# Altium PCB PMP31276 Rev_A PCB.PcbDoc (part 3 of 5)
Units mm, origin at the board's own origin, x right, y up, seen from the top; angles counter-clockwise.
Board outline 228.6 x 203.2 mm, 4 copper layers (Top Layer, Layer 1, Layer 2, Bottom Layer), stack 1.998 mm thick; 375 components, 187 nets, 994 pads, 546 vias.
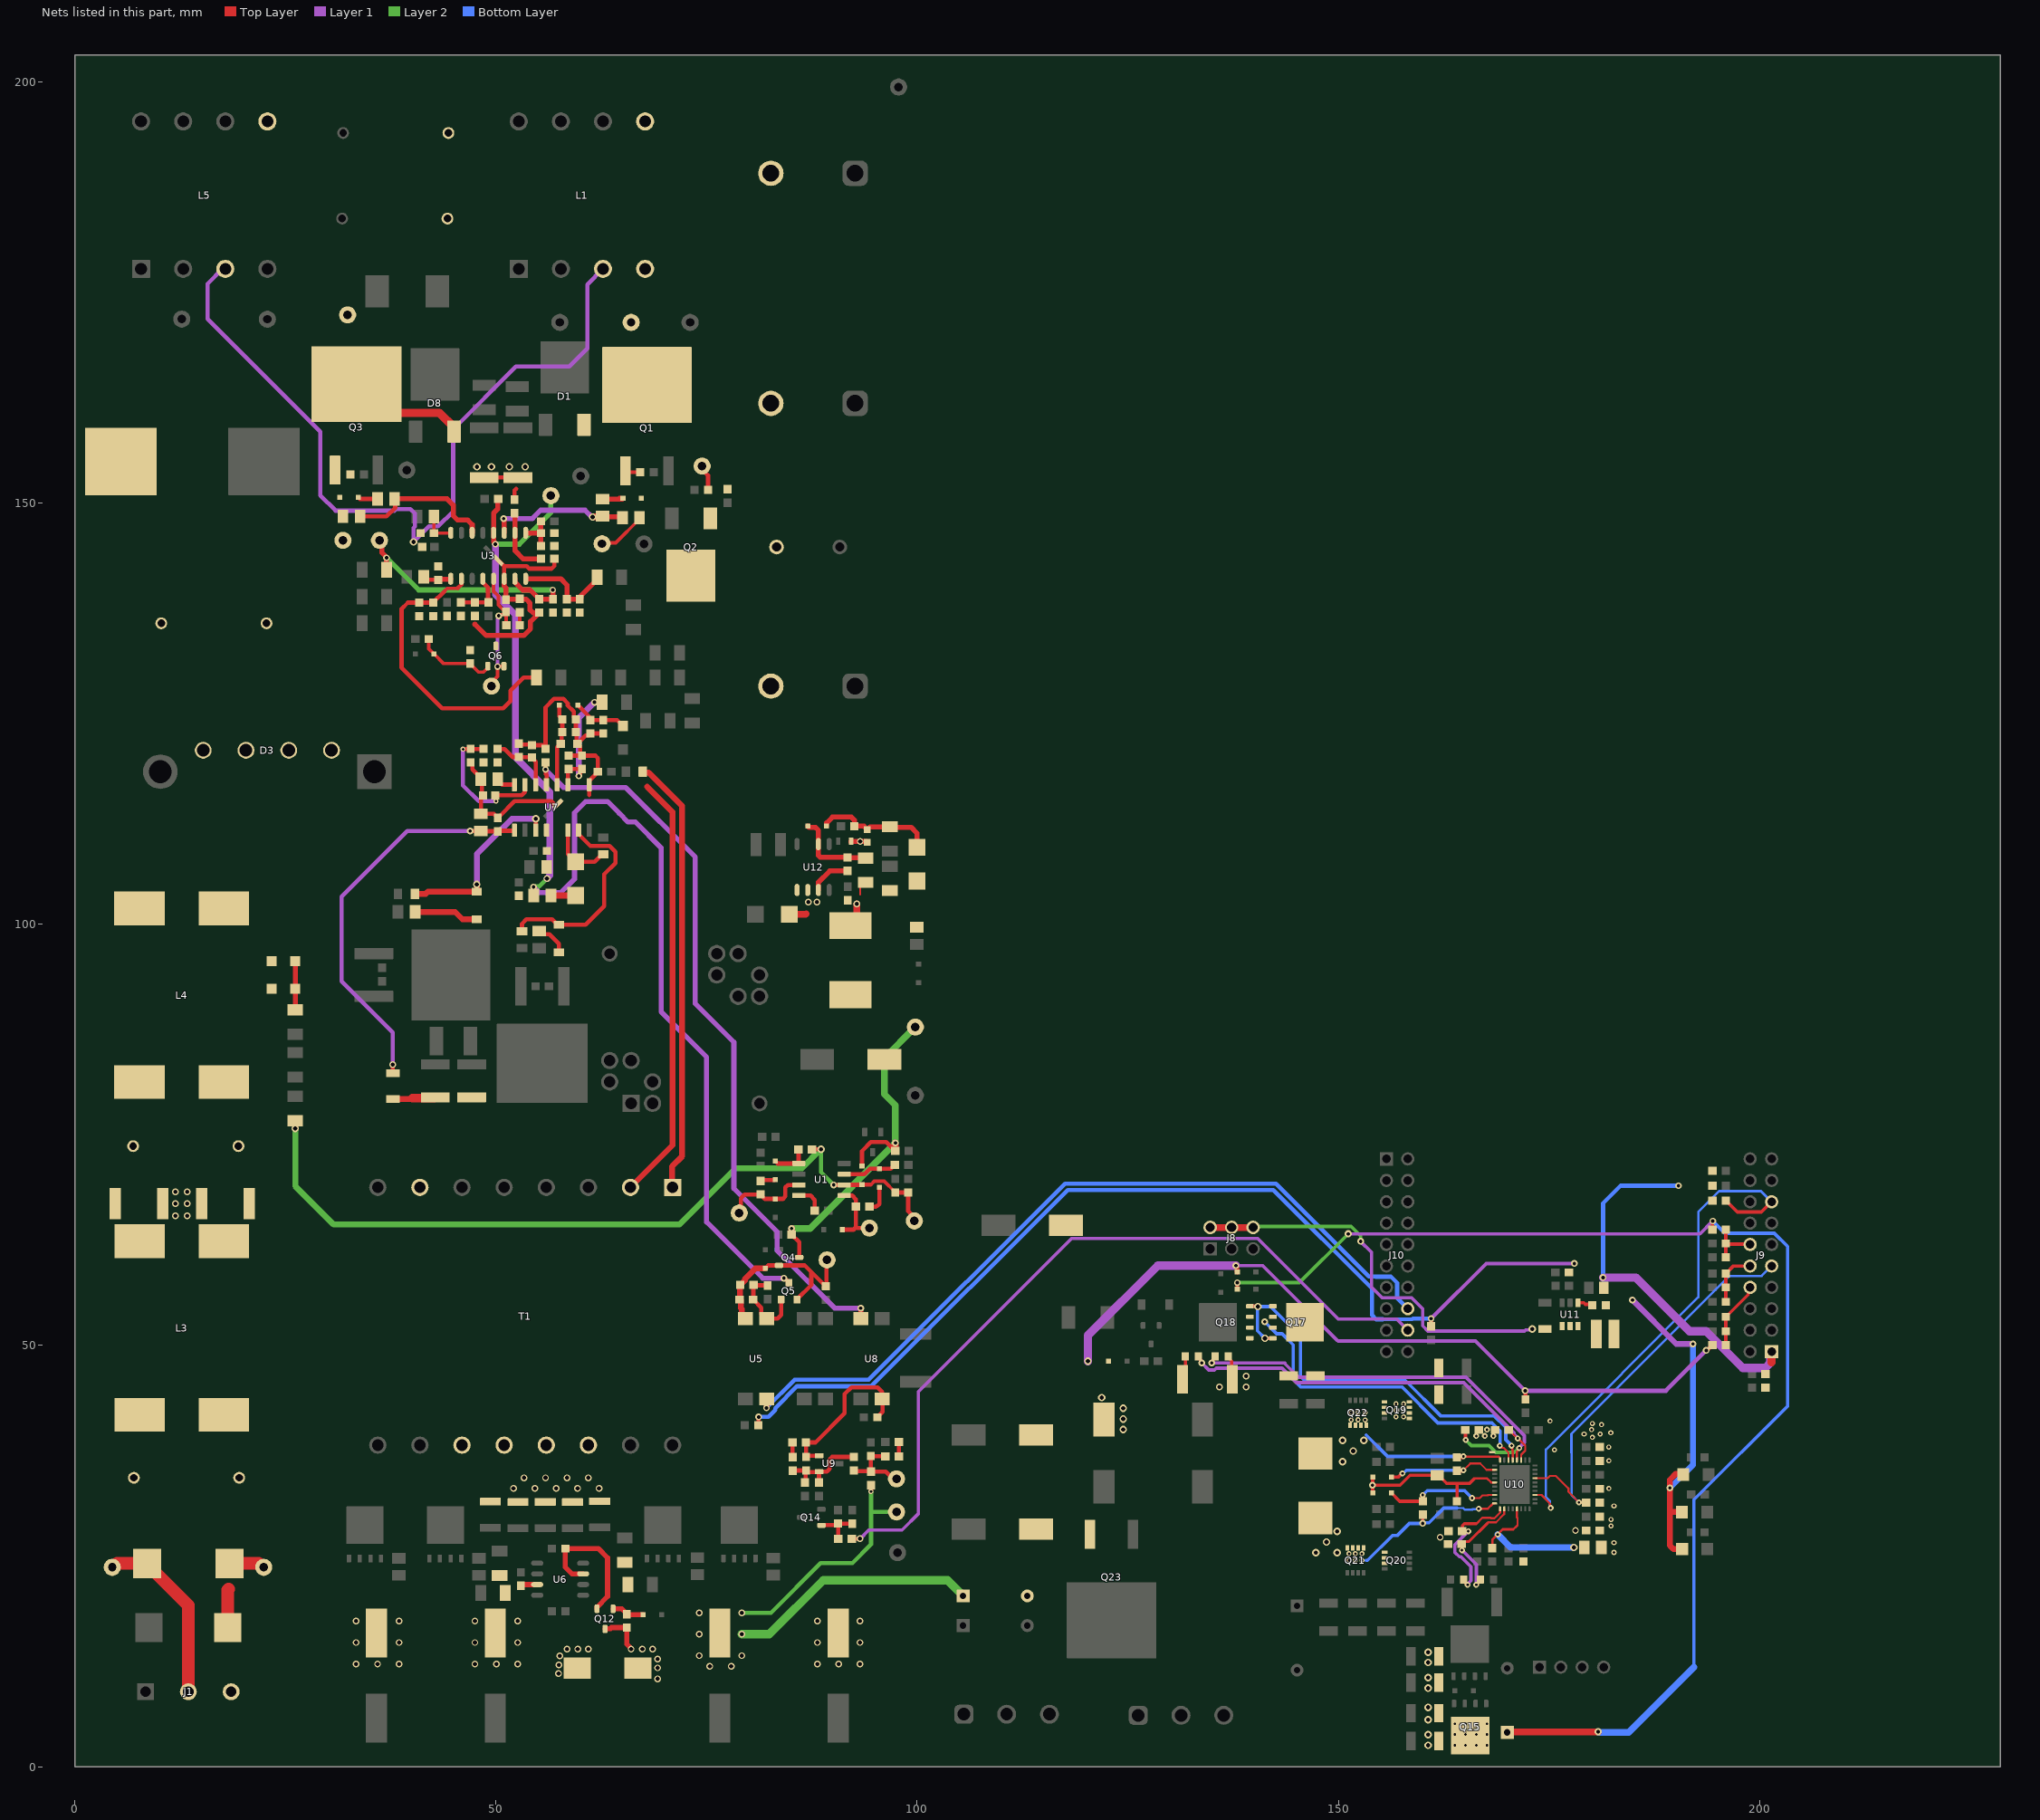
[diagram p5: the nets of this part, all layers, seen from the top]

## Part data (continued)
R100: library part CMP-0025067-3, "RES, 2.58 k, 0.5%, 0.1 W, 0603", Manufacturer="Yageo America", Power_W=100mW, TempCo="50 ppm/C", Tolerance_%=0.5%, Value2=0.1W, Value_Code=2k58, ValueDisplayed=2.58k
R101: library part CMP-0022941-4, "RES, 249 k, 1%, 0.1 W, 0603", Manufacturer=Yageo, Power_W=100mW, Supplier Part Number 1=311-249KHRCT-ND, TempCo="100 ppm/C", Tolerance_%=1%, Value2=0.1W, Value_Code=249k
R103: library part CMP-0025339-3, "RES, 4.22 k, 0.5%, 0.1 W, 0603", Manufacturer="Yageo America", Power_W=100mW, TempCo="50 ppm/C", Tolerance_%=0.5%, Value2=0.1W, Value_Code=4k22, ValueDisplayed=4.22k
R107: library part CMP-0023232-5, "RES, 66.5 k, 1%, 0.1 W, 0603", Manufacturer=Yageo, Power_W=100mW, Supplier Part Number 1=311-66.5KHRCT-ND, TempCo="100 ppm/C", Tolerance_%=1%, Value2=0.1W, Value_Code=66k5, ValueDisplayed=66.5k
R108: library part CMP-0022236-4, "RES, 24.3 k, 1%, 0.1 W, AEC-Q200 Grade 0, 0603", Manufacturer=Vishay-Dale, Power_W=100mW, Supplier Part Number 1=541-24.3KHCT-ND, TempCo="100 ppm/C", Tolerance_%=1%, Value2=0.1W, Value_Code=24k3, ValueDisplayed=24.3k
R109: library part CMP-0023155-5, "RES, 4.99 k, 1%, 0.1 W, 0603", Manufacturer=Yageo, Power_W=100mW, Supplier Part Number 1=311-4.99KHRCT-ND, TempCo="100 ppm/C", Tolerance_%=1%, Value2=0.1W, Value_Code=4k99, ValueDisplayed=4.99k
R110: library part CMP-0016277-2, "RES, 1.00 k, 1%, 0.75 W, AEC-Q200 Grade 0, 2010", Manufacturer=Vishay-Dale, Power_W=750mW, Supplier Part Number 1=541-1.00KACCT-ND, TempCo="100 ppm/C", Tolerance_%=1%, Value2=0.75W, Value_Code=1k00, ValueDisplayed=1.00k
R111: library part CMP-0024096-3, "RES, 30.1 k, 0.1%, 0.1 W, 0603", Manufacturer="Yageo America", Power_W=100mW, TempCo="25 ppm/C", Tolerance_%=0.1%, Value2=0.1W, Value_Code=30k1, ValueDisplayed=30.1k
R112: library part CMP-0024368-2, "RES, 5.23 k, 0.1%, 0.1 W, 0603", Manufacturer="Yageo America", Power_W=100mW, TempCo="25 ppm/C", Tolerance_%=0.1%, Value2=0.1W, Value_Code=5k23, ValueDisplayed=5.23k
R113: library part CMP-0086261-1, "RES, 100 k, 0.5%, 0.1 W, AEC-Q200 Grade 0, 0603", Manufacturer=Vishay-Dale, Power_W=100mW, TempCo="50 ppm/C", Tolerance_%=0.5%, Value2=0.1W, Value_Code=100k
R114 R132: library part CMP-0023167-5, "RES, 51.0 k, 1%, 0.1 W, 0603", Manufacturer=Yageo, Power_W=100mW, Supplier Part Number 1=311-51.0KHRCT-ND, TempCo="100 ppm/C", Tolerance_%=1%, Value2=0.1W, Value_Code=51k0, ValueDisplayed=51.0k
R116 R117: library part CMP-0017472-3, "RES, 237 k, 1%, 0.25 W, AEC-Q200 Grade 0, 1206", Manufacturer=Panasonic, Power_W=250mW, Supplier Part Number 1=P237KFCT-ND, TempCo="100 ppm/C", Tolerance_%=1%, Value2=0.25W, Value_Code=237k
R118: library part CMP-0022851-5, "RES, 18.7 k, 1%, 0.1 W, 0603", Manufacturer=Yageo, Power_W=100mW, Supplier Part Number 1=311-18.7KHRCT-ND, TempCo="100 ppm/C", Tolerance_%=1%, Value2=0.1W, Value_Code=18k7, ValueDisplayed=18.7k
R120: library part CMP-0021276-3, "RES, 47.5, 1%, 0.125 W, AEC-Q200 Grade 0, 0805", Manufacturer=Vishay-Dale, Power_W=125mW, Supplier Part Number 1=541-47.5CCT-ND, TempCo="100 ppm/C", Tolerance_%=1%, Value2=0.125W, Value_Code=47R5, ValueDisplayed=47.5
R125 R127 R128: library part CMP-0022746-5, "RES, 10.0 k, 1%, 0.1 W, 0603", Manufacturer=Yageo, Power_W=100mW, Supplier Part Number 1=311-10.0KHRCT-ND, TempCo="100 ppm/C", Tolerance_%=1%, Value2=0.1W, Value_Code=10k0, ValueDisplayed=10.0k
R126 R129 R130: library part CMP-0022008-4, "RES, 110 k, 1%, 0.1 W, AEC-Q200 Grade 0, 0603", Manufacturer=Vishay-Dale, Power_W=100mW, Supplier Part Number 1=541-110KHCT-ND, TempCo="100 ppm/C", Tolerance_%=1%, Value2=0.1W, Value_Code=110k
RT1: library part CMP-0002554-2, "Thermistor NTC, 22 ohm, 20%, 15x7mm", Manufacturer=TDK, Power_W=3.1W, Supplier Part Number 1=495-3054-ND, Tolerance_%=20%
RV1: library part CMP-0002101-2, "Varistor, 275VAC, 1200A, SMD", Manufacturer=Littelfuse, Supplier Part Number 1=F3550CT-ND
T1: library part CMP-0120632-1, "TRANSFORMER", Manufacturer=Wurth, Operating Temperature Range="-40°C to +125°C"
TP1 TP2 TP17 TP23 TP26: library part CMP-0055137-2, "Test Point, Miniature, Red, TH", Color=Red, Manufacturer="Keystone Electronics", Supplier Part Number 1=36-5000-ND
TP3 TP6 TP10 TP11 TP12 TP13 TP14 TP16 TP18 TP19 TP20 TP21 TP22 TP25: library part CMP-0055141-2, "Test Point, Miniature, Yellow, TH", Color=Yellow, Manufacturer="Keystone Electronics", Supplier Part Number 1=36-5004-ND
TP4 TP7 TP9 TP15 TP24 TP27: library part CMP-0055138-2, "Test Point, Miniature, Black, TH", Color=Black, Manufacturer="Keystone Electronics", Supplier Part Number 1=36-5001-ND
TP5 TP8: library part CMP-0055139-2, "Test Point, Miniature, White, TH", Color=White, Manufacturer="Keystone Electronics", Supplier Part Number 1=36-5002-ND
U1: library part CMP-0089002-1, "Dual Rail-to-rail Comparator with push-pull outputs, 8-SOIC", Manufacturer="Texas Instruments", Operating Temperature Range="-40°C to +125°C"
U2: library part CMP-0033016-1, "Precision Micropower Shunt Voltage Reference, 1% accuracy, 5 V, 15 ppm / degC, 15 mA, -40 to 125 degC, 3-pin SOT-23 (DBZ), Green (RoHS & no Sb/Br)", Manufacturer="Texas Instruments", Rating=Catalog, Temp Coeff(Max)(ppm/ degree C)=150, Temp Coeff(Typ)(ppm/ degree C)=15
U3: library part CMP-0861100-1, "Natural Interleaving Transition Mode PFC Controller with High Light Load Efficiency Supporting High-Frequency Switching up-to 1MHz, D0016A (SOIC-16)", Alternate Manufacturer="Texas Instruments"
U4 U5 U8: library part CMP-0006172-3, "Optocoupler, 5.3 kV, 63-125% CTR, SMT", Manufacturer=Vishay-Semiconductor, Supplier Part Number 1=751-1346-1-ND, Voltage_Isolation_Vrms=5.3kV
U6: library part CMP-0079610-1, "High Performance Synchronous Rectifier Driver for LLC Resonant Converter, D0008A (SOIC-8)", Alternate Manufacturer="Texas Instruments"
U7: library part CMP-0095299-1, "750kHz Wide VIN/VOUT Range LLC Controller Optimized for Light Load Efficiency", Manufacturer="Texas Instruments", Max Supply Voltage=18.5V, Operating Temperature Range="-40°C to +150°C", Switching Frequency=30-750kHz
U9: library part CMP-0084733-1, "High Bandwidth Low-Iq Programmable Shunt Regulator, DBZ0003A (SOT-23-3)", Alternate Manufacturer="Texas Instruments"
U10: library part CMP-0093459-1, Manufacturer="Texas Instruments", Operating Temperature Range=to
U11: library part CMP-0065097-3, "4V to 36 V 0.6 A Synchronous Step-Down Converter, DBV0006A (SOT-23-6)", Alternate Manufacturer="Texas Instruments", Alternate PartNumber=TPS560430XDBVT
U12: library part CMP-0067241-2, "700V Flyback Switcher with Constant-Voltage Constant-Current and Primary-side Control, D0007A (SOIC-7)", Alternate Manufacturer="Texas Instruments", Alternate PartNumber=UCC28910D

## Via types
v1: diameter 0.8, hole 0.5, Top Layer to Bottom Layer, tented both sides, 185 vias
v2: diameter 0.9, hole 0.5, Top Layer to Bottom Layer, tented both sides, 166 vias
v3: diameter 0.6, hole 0.3, Top Layer to Bottom Layer, tented both sides, 64 vias
v4: diameter 0.8, hole 0.4, Top Layer to Bottom Layer, tented both sides, 55 vias
v5: diameter 0.7, hole 0.3, Top Layer to Bottom Layer, tented both sides, 55 vias
v6: diameter 0.5, hole 0.2, Top Layer to Bottom Layer, 16 vias
v7: diameter 0.9, hole 0.5, Top Layer to Bottom Layer, tented bottom, 3 vias
v8: diameter 0.864, hole 0.406, Top Layer to Bottom Layer, tented both sides, 2 vias

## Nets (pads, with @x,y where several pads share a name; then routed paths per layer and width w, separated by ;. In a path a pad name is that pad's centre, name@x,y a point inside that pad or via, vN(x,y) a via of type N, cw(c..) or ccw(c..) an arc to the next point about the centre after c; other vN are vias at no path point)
3V3: C93.1 C99.1 C100.2 D26.2 D27.2 D28.2 J9.1 L9.2 R39.2 R114.2 R121.2 R122.2 R123.2 R131.2 | length 207.2
  Top Layer w0.5: R39.2@81.135,40.513 81.161,40.539 81.161,41.479 v4(81.187,41.505) ; R131.2@161.006,52.258 v4(161.006,53.187)
  Top Layer w0.7: D26.2@190.778,30.226 189.434,30.226 189.357,30.149 ; D27.2@190.805,25.832 189.767,25.832 189.357,26.242 189.357,30.149 ; D28.2@190.924,34.668 190.816,34.776 190.078,34.776 189.357,34.055 v4(189.357,33.092) 189.357,30.149
  Top Layer w1: 201.422,48.006 J9.1@201.422,49.276
  Layer 1 w0.45: v4(161.006,53.187) 167.546,59.727 v4(178.004,59.727)
  Layer 1 w0.7: v4(184.912,55.379) 190.118,50.173 v4(192.109,50.173)
  Layer 1 w1: v4(181.419,58.055) 185.317,58.055 191.684,51.689 193.649,51.689 198.004,47.334 200.686,47.334 201.295,47.942 201.295,49.149 J9.1@201.422,49.276
  Bottom Layer w0.45: 155.286,53.105 155.299,53.092 158.766,53.092 158.86,53.187 v4(161.006,53.187)
  Bottom Layer w0.5: v4(81.187,41.505) 81.211,41.528 82.337,41.528 83.138,42.329 83.138,42.541 85.757,45.16 94.559,45.16 117.859,68.461 142.293,68.461 153.993,56.761 153.993,53.597 154.484,53.105 155.286,53.105 ; v4(181.419,58.055) 181.419,66.865 183.515,68.961 v4(190.373,68.961)
  Bottom Layer w0.7: v4(189.357,33.092) 192.109,35.845 v4(192.109,50.173)
5Vp: C52.1 R64.1 R69.1 U7.8 | length 2.3
  Top Layer w0.5: C52.1@50.216,117.24 50.216,117.075 50.721,116.57 U7.8@52.181,116.57
15Vp: C98.1 D9.1 D35.2 L10.2 Q4.3 R10.2 R12.2 R117.2 R120.2 TP26.1 | length 43.7
  Top Layer w0.5: R12.2@85.088,63.148 85.113,63.148 85.988,62.273 Q4.3@85.988,60.452 ; D9.1@93.448,71.283 93.448,73.069 94.517,74.138 96.327,74.138 97.365,73.1 R10.2@97.39,73.1
  Top Layer w0.8: R12.2@85.088,63.148 85.09,63.15 v4(85.09,63.881) ; R10.2@97.39,73.1 97.418,73.128 v4(97.418,74.027)
  Layer 2 w0.8: v4(85.09,63.881) 87.272,63.881 v4(97.418,74.027) 97.418,78.528 96.084,79.862 96.084,84.094 TP26.1@99.78,87.79
15Vp-sw: C19.1 C48.1 C49.1 C50.1 Q5.3 R63.2 TP17.1 U3.12 U7.12 | length 147.7
  Top Layer w0.5: v4(54.445,104.424) 54.464,104.405 54.464,103.427 R63.2@54.483,103.408 ; v4(84.179,57.992) 84.236,57.934 84.352,57.934 84.788,57.498 Q5.3@84.788,57.448
  Top Layer w0.6: v4(49.923,145.118) 49.923,145.172 49.71,145.385 U3.12@49.71,146.461 49.71,148.8 50.209,149.299 50.209,150.427 C19.1@50.263,150.481
  Layer 1 w0.6: v4(54.445,104.424) 54.499,104.424 55.148,103.775 57.724,103.775 59.32,105.371 59.32,113.24 60.648,114.568 63.235,114.568 64.622,113.181 64.622,113.175 65.667,112.13 66.556,112.13 69.603,109.083 69.603,89.626 75.008,84.222 75.008,64.653 81.669,57.992 v4(84.179,57.992) ; TP17.1@56.481,150.842 TP17.1@56.515,150.876
  Layer 1 w0.8: v4(49.923,145.118) 49.923,139.099 52.287,136.734 52.287,119.822 56.409,115.7 56.409,105.792 v1(56.049,105.431)
  Layer 2 w0.5: v4(54.445,104.424) 54.502,104.481 55.099,104.481 v1(56.049,105.431)
  Layer 2 w0.6: v4(49.923,145.118) 52.775,145.118 56.515,148.858 TP17.1@56.515,150.876
24V/27.6V: J10.39 R84.1 | length 93.8
  Top Layer w0.4: R84.1@92.24,27.051 v1(93.218,27.051)
  Layer 1 w0.4: v1(93.218,27.051) 94.251,28.084 98.199,28.084 100.152,30.038 100.152,44.526 118.323,62.697 140.429,62.697 149.983,53.142 156.916,53.142 J10.39@158.242,51.816
+24V: C38.1 C64.1 C65.1 C66.1 C67.1 C85.1 C86.2 D32.2 J6.1 J11.1 L7.2 Q12.3 Q15.5 Q15.6 Q15.7 Q15.8 Q15.9@165.648,3.685 R60.2 R65.2 R99.2 R126.1 TP23.1 U10.33 | length 231.6
  Top Layer w0.25: 170.748,28.156 170.981,28.389 170.992,28.389 171.272,28.668 171.272,29.503 171.191,29.584 U10.33@171.191,30.595
  Top Layer w0.3: R99.2@168.275,25.946 168.275,26.924 v5(168.91,27.559) 169.507,28.156 170.748,28.156
  Top Layer w0.35: R99.2@168.02,26.04 R99.2@168.02,26.065
  Top Layer w0.4: D32.2@138.002,56.681 v4(138.002,57.456) ; R126.1@194.399,63.754 194.418,63.773 194.418,64.751 v4(194.437,64.77)
  Top Layer w0.5: v3(94.517,32.664) R65.2@94.517,33.414
  Top Layer w0.6: Q12.3@62.944,16.345 62.944,16.369 63.586,16.369 63.721,16.504 R60.2@65.535,16.504 65.535,14.529 66.04,14.024 v1(66.04,13.97)
  Top Layer w0.8: J11.1@170.053,4.064 170.116,4.127 180.833,4.127 v8(180.845,4.14)
  Layer 1 w0.4: v8(151.158,63.246) 192.913,63.246 v4(194.437,64.77)
  Layer 2 w0.4: v4(138.002,57.456) 145.367,57.456 v8(151.158,63.246)
  Layer 2 w0.5: v1(79.193,18.255) 82.643,18.255 88.543,24.155 92.32,24.155 94.517,26.353 94.517,30.226 ; v3(94.517,32.664) 94.517,30.226 ; TP23.1@97.536,30.226 94.517,30.226
  Layer 2 w1: v1(79.193,15.715) 82.428,15.715 88.838,22.125 103.595,22.125 J6.1@105.453,20.267
  Bottom Layer w0.4: 192.211,11.811 192.211,31.683 203.327,42.799 203.327,61.747 201.752,63.322 195.885,63.322 v4(194.437,64.77)
  Bottom Layer w0.8: v5(168.91,27.559) 170.448,26.021 v2(177.953,26.021) ; v8(180.845,4.14) 180.921,4.064 184.464,4.064 192.211,11.811
  other v1: 69.182,10.429 69.182,11.726 75.383,11.905 77.923,11.905 69.182,12.763 74.113,13.175 79.193,13.175 67.374,13.97 68.58,13.97 74.113,15.715 74.113,18.255 178.15,28.02
  other v2: 160.655,2.54 160.655,3.81 160.655,5.581 160.655,7.04 160.655,9.312 160.655,10.583 160.655,12.368 160.655,13.581
  other v3: 163.83,2.54 165.1,2.54 166.37,2.54 167.64,2.54 163.83,3.81 165.1,3.81 166.37,3.81 167.64,3.81 163.83,5.08 165.1,5.08 166.37,5.08 167.64,5.08
+24Vsw: C8.2 C12.2 C35.1 C36.1 C37.1 C39.2 C40.2 C41.2 L7.1 T1.11 T1.12 T1.13 T1.14
  other v1: 57.435,11.066 57.484,12.088 33.401,12.192 35.941,12.192 38.481,12.192 47.498,12.192 50.038,12.192 52.578,12.192 88.138,12.192 90.678,12.192 93.218,12.192 57.568,13.166 58.42,13.97 59.702,13.97 60.96,13.97 33.401,14.732 38.481,14.732 47.498,14.732 52.578,14.732 88.138,14.732 93.218,14.732 33.401,17.272 38.481,17.272 47.498,17.272 52.578,17.272 88.138,17.272 93.218,17.272 52.07,33.02 54.61,33.02 57.15,33.02 59.69,33.02 62.23,33.02 53.34,34.29 55.88,34.29 58.42,34.29 60.96,34.29
AC_DC_on: J10.38 U5.2 | length 95.5
  Top Layer w0.5: U5.2@82.11,43.628 U5.2@82.145,43.663
  Top Layer w0.7: v4(82.11,42.58) U5.2@82.11,43.628
  Bottom Layer w0.5: v4(82.11,42.58) 85.445,45.914 94.246,45.914 117.547,69.215 142.605,69.215 153.624,58.195 154.392,58.195 154.428,58.16 156.225,58.16 156.978,57.407 156.978,55.62 J10.38@158.242,54.356
AGND: C69.2 C70.1 C82.1 C83.2 C85.2 C86.1 NT1.2 R103.1 R107.1 R108.1 R109.1 R111.1 R124.1
  other v1: 162.077,27.231
  other v3: 182.719,25.432 182.719,26.584 182.372,28.569 182.372,29.337 182.719,30.949 182.118,33.02 182.118,36.322 175.641,37.592 182.091,37.945 180.144,39.089 179.166,39.48 181.087,39.48 182.339,39.625 180.058,40.005 181.228,40.597 180.144,40.736 175.133,41.021
  other v5: 166.37,39.243 167.386,39.243 168.402,39.243 167.64,40.005
AGND1: C18.2 C20.2 C21.2 C22.2 C23.2 C24.1 C25.2 C26.2 C28.1 C29.2 C30.2 C31.2 L1.3 L5.3 NT2.2 Q6.3 R26.1 R33.1 R40.1 R41.1 R42.1 R46.1 U3.6 | length 122.5
  Top Layer w0.5: NT2.2@50.255,143.208 50.255,143.203 50.96,142.498 ; U3.6@50.961,141.031 U3.6@50.98,141.011 ; U3.6@50.98,141.031 50.98,142.478 50.96,142.498 ; C20.2@56.934,143.383 56.934,142.536 56.615,142.217 53.928,142.217 53.647,142.498 50.96,142.498
  Top Layer w0.6: 47.498,135.603 48.836,134.265 53.283,134.265 54.094,135.077 54.094,135.946 55.118,136.97 C23.2@55.118,136.995 55.044,137.069 54.957,136.982 54.381,136.982 54.047,137.316 54.047,138.105 53.557,138.595 52.87,138.595 C26.2@52.832,138.633 52.776,138.577 51.237,138.577 C24.1@51.181,138.521 51.181,139.924 50.98,140.125 U3.6@50.98,141.011
  Layer 1 w0.5: L5.3@17.86,177.8 17.526,177.8 15.748,176.022 15.748,171.876 29.155,158.469 29.155,150.894 30.95,149.099 37.96,149.099 38.16,149.299 39.839,149.299 40.366,148.772 40.366,147.216 40.195,147.046 v2(40.195,145.382) 42.036,147.222 43.121,147.222 44.921,149.022 44.921,158.768 52.375,166.222 58.717,166.222 60.851,168.356 60.851,175.95 L1.3@62.701,177.8
AGND2: C52.2 C53.1 C55.2 C56.1 C57.2 C58.2 C59.2 C60.2 NT3.2 R58.1 R67.1 R75.1 R76.1 R77.1 R79.1 R80.2 R82.1 T1.2 U7.1 | length 99.2
  Top Layer w0.5: R75.1@46.989,119.215 47.214,118.99 47.214,118.376 48.184,117.406 C52.2@48.184,117.24 48.327,117.097 48.327,115.445 C56.1@48.47,115.302 48.446,115.302 48.211,115.067 R58.1@48.211,113.106 49.746,113.106 C55.2@50.209,112.643 ; C55.2@50.209,112.618 C55.2@50.209,112.643 ; R67.1@52.705,121.45 52.806,121.349 54.147,121.349 C53.1@54.248,121.249 54.256,121.256 55.464,121.256 C59.2@55.88,120.84 ; C59.2@55.88,120.815 C59.2@55.88,120.84 ; NT3.2@57.693,114.613 NT3.2@57.334,114.254 57.116,114.036 57.11,114.036 56.533,114.613 52.204,114.613 50.459,112.868 50.434,112.868 C55.2@50.209,112.643 ; R76.1@58.62,120.017 C57.2@60.2,120.017 ; 61.071,115.35 U7.1@61.071,116.57 61.071,117.045 61.836,117.81 61.836,117.885 62.061,118.11 R82.1@62.086,118.11 62.086,119.724 61.793,120.017 C57.2@60.2,120.017 ; C60.2@62.738,122.644 R80.2@61.214,122.644 61.214,122.619 60.989,122.394 60.656,122.394 R77.1@59.674,121.412 ; C59.2@55.88,120.84 55.88,125.74 56.892,126.752 57.995,126.752 58.517,126.229 58.517,125.957 59.224,125.249 59.224,124.558 59.449,124.333 R79.1@59.474,124.333 C58.2@59.474,122.809 59.574,122.709 59.574,121.512 R77.1@59.674,121.412 ; R77.1@59.674,121.412 59.975,121.111 59.975,120.242 C57.2@60.2,120.017
  Top Layer w0.7: T1.2@65.967,68.767 70.967,73.767 70.967,113.302 67.957,116.312
AUX: R73.2 T1.1 | length 52.3
  Top Layer w0.5: 68.121,118 68.121,118.125 ; T1.1@70.912,68.822 T1.1@70.967,68.767
  Top Layer w0.7: R73.2@67.421,118.11 67.531,118 68.121,118 72.104,114.017 72.104,72.463 70.912,71.271 T1.1@70.912,68.822
AUX_15V: C15.1 U1.8 | length 3.4
  Top Layer w0.5: U1.8@85.946,67.789 87.343,67.789 87.846,67.285 C15.1@87.846,66.002
BAT: C88.1 C89.1 C90.1 D25.1 D33.2 J6.2 Q23.3 R96.1 R97.1 R101.1 R129.2 | length 93.8
  Top Layer w0.4: R96.1@131.504,45.974 131.854,46.324 R97.1@131.854,48.705
  Top Layer w0.5: v4(137.83,59.476) 137.83,59.395 137.952,59.272 137.952,58.751 D33.2@138.002,58.701 ; v4(172.171,44.62) 172.191,44.6 172.191,43.62 R101.1@172.212,43.599 ; v4(193.675,49.403) 193.744,49.403 194.374,50.033 R129.2@194.399,50.033
  Layer 1 w0.4: v4(137.83,59.476) 141.006,59.476 149.836,50.646 149.967,50.515 166.276,50.515 v4(172.171,44.62)
  Layer 1 w0.5: v4(172.171,44.62) 188.892,44.62 v4(193.675,49.403)
  Layer 1 w1: v2(120.268,48.132) 120.268,51.184 128.559,59.476 v4(137.83,59.476)
BAT_DRV: Q17.4 Q18.4 U10.15 | length 48.4
  Top Layer w0.25: v5(170.561,38.1) 170.647,38.014 170.647,37.547 170.699,37.496 170.699,36.764 170.691,36.756 U10.15@170.691,36.395
  Top Layer w0.45: Q18.4@139.499,54.662 140.41,54.662 v2(140.462,54.61) ; v2(141.278,50.852) Q17.4@142.228,50.852
  Bottom Layer w0.4: v2(141.278,50.852) 140.402,51.728 140.402,54.55 v2(140.462,54.61) 141.956,54.61 145.51,51.057 145.51,46.313 145.993,45.83 157.966,45.83 162.177,41.619 168.542,41.619 169.86,40.3 169.86,38.801 v5(170.561,38.1)
BAT_SRC: Q17.1 Q17.2 Q17.3 Q18.1 Q18.2 Q18.3 U10.16 | length 39.4
  Top Layer w0.25: v5@169.391,37.844 169.637,37.844 170.195,37.287 170.195,36.872 170.191,36.872 U10.16@170.191,36.395
  Bottom Layer w0.4: v4(141.256,52.807) 142.667,51.396 143.309,51.396 144.643,50.061 144.643,45.952 145.51,45.085 157.539,45.085 161.815,40.809 168.243,40.809 169.206,39.846 169.206,38.142 v5(169.164,38.1)
BQ_CE: J9.5 R124.2 U10.7 | length 48.2
  Top Layer w0.25: U10.7@173.341,34.245 174.85,34.245 175.116,34.511 175.816,34.511 177.308,33.019 177.308,32.623 v5(178.562,31.369)
  Top Layer w0.4: v5(178.562,31.369) 178.579,31.352 179.395,31.352 R124.2@179.412,31.336
  Bottom Layer w0.25: 177.677,37.271 177.677,32.254 v5(178.562,31.369)
  Bottom Layer w0.3: 177.677,37.271 177.677,39.496 196.428,58.247 200.233,58.247 J9.5@201.422,59.436
BQ_INT: J9.8 R123.1 U10.3 | length 62.4
  Top Layer w0.25: U10.3@173.341,32.245 174.102,32.245 175.109,31.237 175.109,30.787 v5(175.195,30.701)
  Top Layer w0.4: R123.1@195.999,67.183 196.024,67.183 197.365,65.842 200.208,65.842 J9.8@201.422,67.056
  Bottom Layer w0.3: v5(175.195,30.701) 175.119,30.777 175.119,31.496 174.636,31.978 174.636,37.64 192.73,55.733 192.73,65.857 195.199,68.326 200.152,68.326 J9.8@201.422,67.056
COMP: C24.2 Q6.2 R34.2 TP22.1 U3.5 | length 16.7
  Top Layer w0.4: TP22.1@49.463,128.27 49.463,128.712 50.186,129.434 v4(50.186,130.596) 50.209,130.62 50.913,130.62 Q6.2@50.936,130.643 ; U3.5@49.71,141.011 49.71,139.525 50.281,138.953 50.281,137.9 50.809,137.372 50.902,137.372 51.181,137.093 C24.2@51.181,137.069 ; v4(50.314,136.614) 50.422,136.614 50.574,136.766 50.902,136.766 51.181,137.045 C24.2@51.181,137.069 ; R34.2@51.219,135.484 51.2,135.503 51.2,137.05 C24.2@51.181,137.069
  Layer 1 w0.4: v4(50.186,130.596) 50.186,136.198 50.237,136.249 50.237,136.537 v4(50.314,136.614)
CS: C5.1 C6.1 C7.1 D3.4 R4.2 R5.2 R28.1 | length 5.4
  Top Layer w0.5: R5.2@48.599,153.035 R4.2@52.6,153.035 ; R28.1@52.197,150.406 52.197,151.511 52.392,151.706
  other v2: 47.752,154.305 49.462,154.305 51.585,154.305 53.467,154.305
DRV_SUP: C84.1 D23.2 D24.2 R98.2 U10.23 | length 19.9
  Top Layer w0.25: 166.115,34.163 166.184,34.232 167.627,34.232 168.115,33.745 U10.23@168.541,33.745
  Top Layer w0.4: D23.2@154.093,32.485 154.072,32.505 154.072,33.38 v4(154.051,33.401) ; D24.2@154.093,34.384 154.072,34.363 154.072,33.422 v4(154.051,33.401) ; R98.2@164.083,31.501 164.083,33.498 164.21,33.625 ; 166.115,34.163 165.578,33.625 164.21,33.625 ; v4(154.051,33.401) 157.311,33.401 158.496,34.586 C84.1@161.731,34.586 161.896,34.586 162.747,33.735 162.747,33.722 162.843,33.625 164.21,33.625
EARTH: C9.2 C13.1 J1.3
  other v1: 11.938,65.405 13.335,65.405 11.938,66.847 13.335,66.847 11.938,68.247 13.335,68.247
FB: C59.1 U7.5 U8.4 | length 89.8
  Top Layer w0.5: U7.5@55.991,116.57 56.007,116.587 56.007,117.704 55.937,117.773 55.937,118.307 v4(55.88,118.364) C59.1@55.88,119.215 C59.1@56.007,119.088
  Top Layer w0.6: v4(93.296,54.427) 93.309,54.413 93.309,53.201 U8.4@93.322,53.188
  Layer 1 w0.6: v4(55.88,118.364) 58.012,116.232 65.387,116.232 73.654,107.965 73.654,90.583 78.235,86.002 78.235,68.641 83.363,63.513 83.363,61.271 90.208,54.427 v4(93.296,54.427) v4@93.257,54.465
GDA: R15.1 R18.1 U3.14 | length 17.9
  Top Layer w0.5: R18.1@33.87,148.418 37.004,148.418 38.044,149.458 38.044,150.411 R15.1@37.96,150.495
  Top Layer w0.6: R15.1@37.96,150.495 44.192,150.495 44.935,149.753 44.935,148.966 44.925,148.956 44.925,148.491 45.446,147.971 46.636,147.971 47.17,147.436 U3.14@47.17,146.461
GDB: R1.1 R3.1 U3.11 | length 16.7
  Top Layer w0.6: v4(50.923,148.165) 50.923,148.111 50.98,148.054 U3.11@50.98,146.461 ; R1.1@62.275,148.436 62.356,148.355 R1.1@62.363,148.348 ; R1.1@62.744,148.348 R3.1@64.532,148.348 ; R3.1@64.62,148.26 R3.1@64.532,148.348 ; R3.1@64.913,148.348 R3.1@64.532,148.348
  Top Layer w0.8: v2(61.468,148.336) 61.487,148.355 62.356,148.355 62.575,148.355 R1.1@62.656,148.436
  Layer 1 w0.6: v4(50.923,148.165) 54.325,148.165 55.308,149.149 60.574,149.149 61.387,148.336 v2(61.468,148.336)
HDRV-G: D16.1 R51.1 U7.15 | length 24.7
  Top Layer w0.5: R51.1@53.086,99.171 53.086,100.059 53.611,100.584 56.676,100.584 57.306,99.954 D16.1@57.459,99.954 60.645,99.954 62.845,102.154 62.845,105.939 64.168,107.263 64.168,108.608 63.483,109.292 61.204,109.292 59.801,110.695 U7.15@59.801,111.17
ISNS: C42.1 C55.1 R58.2 U7.9 | length 47.3
  Top Layer w0.5: C42.1@37.75,82.336 v1(37.75,83.339) ; v4(46.944,111.074) R58.2@48.211,111.074 48.239,111.046 50.181,111.046 C55.1@50.209,111.018 50.285,111.094 52.131,111.094 52.181,111.144 U7.9@52.181,111.17
  Layer 1 w0.5: v1(37.75,83.339) 37.75,87.156 31.677,93.229 31.677,103.267 39.483,111.074 v4(46.944,111.074)
LDRV-G: D17.1 R56.1 U7.11 | length 22
  Top Layer w0.5: U7.11@54.721,111.17 v2(54.721,112.522)
  Top Layer w0.7: R56.1@40.37,103.603 41.656,103.603 41.912,103.859 D17.1@47.715,103.859 v2(47.715,104.727)
  Layer 1 w0.7: v2(47.715,104.727) 47.715,108.339 51.898,112.522 v2(54.721,112.522)
net_D1_3: D1.3 L1.4 L1.5 Q1.2 TP3.1
NetC1_2: C1.2 C2.2 C3.2 Q2.2 RT1.2
NetC6_2: C6.2 D3.1 L2.1
NetC9_1: C9.1 C10.2 L3.2 L4.1
NetC10_1: C10.1 C13.2 L3.3 L4.4
NetC11_1: C11.1 J1.2 L3.4 RV1.1 TP8.1 | length 21.6
  Top Layer w1.5: TP8.1@4.447,23.667 4.591,23.667 5.055,24.13 RV1.1@8.577,24.13 8.577,24.03 13.477,19.13 J1.2@13.477,8.89
NetC11_2: C11.2 F1.2 L3.1 RV1.2 TP5.1 | length 9.2
  Top Layer w1.5: F1.2@18.265,16.622 F1.2@18.152,16.51 18.152,20.959 18.275,21.082 ; RV1.2@18.265,24.018 RV1.2@18.377,24.13 21.82,24.13 22.283,23.667 TP5.1@22.427,23.667
NetC14_1: C14.1 Q2.1 R6.1 TP10.1 | length 3.1
  Top Layer w0.5: TP10.1@74.472,154.395 74.472,153.98 75.17,153.282 C14.1@75.17,151.566
NetC17_1: C17.1 D9.2 R14.1 R20.2 R22.2 TP14.1 U1.2 | length 95
  Top Layer w0.4: 94.498,69.083 94.905,69.49 96.084,69.49 97.389,68.186 R20.2@97.389,68.161
  Top Layer w0.5: R22.2@87.501,73.262 87.523,73.284 88.543,73.284 v2(88.565,73.306) ; v4(90.079,69.059) U1.2@91.346,69.059 91.359,69.071 93.436,69.071 D9.2@93.448,69.083 94.498,69.083 ; R20.2@97.389,68.161 C17.1@98.933,68.161 98.933,65.925 99.662,65.196 TP14.1@99.662,64.781
  Top Layer w0.7: v2(26.162,75.774) R14.1@26.162,76.674
  Layer 2 w0.5: v2(88.565,73.306) 88.565,70.572 v4(90.079,69.059)
  Layer 2 w0.7: v2(26.162,75.774) 26.162,68.917 30.734,64.345 71.764,64.345 78.461,71.042 86.302,71.042 v2(88.565,73.306)
NetC18_1: C18.1 R21.1 R26.2 U3.2 | length 36.2
  Top Layer w0.4: 43.861,139.525 44.201,139.864 45.416,139.864
  Top Layer w0.5: 43.861,139.525 43.861,139.522 42.545,138.206 R26.2@42.545,138.181 C18.1@40.894,138.181 39.542,138.181 38.785,137.423 38.785,130.461 43.61,125.636 50.858,125.636 51.724,126.502 51.724,127.729 53.281,129.286 R21.1@54.811,129.286 ; 45.416,139.864 45.881,140.329 45.881,140.992 U3.2@45.9,141.011
NetC20_1: C20.1 R28.2 U3.10 | length 8
  Top Layer w0.6: R28.2@52.197,148.806 52.25,148.753 U3.10@52.25,146.461 52.25,144.346 53.213,143.383 C20.1@55.334,143.383
NetC21_1: C21.1 R30.1 U3.16 | length 4
  Top Layer w0.4: R30.1@42.635,148.401 42.646,148.391 C21.1@42.646,146.431 42.661,146.446 44.615,146.446 U3.16@44.63,146.461
NetC22_1: C22.1 R31.1 U3.1 | length 3.4
  Top Layer w0.5: R31.1@41.435,141.248 41.803,140.88 C22.1@43.136,140.88
  Top Layer w0.6: C22.1@43.136,140.88 43.202,140.946 44.63,140.946 U3.1@44.63,141.011
NetC23_1: C23.1 R29.1 R33.2 TP19.1 U3.7 | length 32
  Top Layer w0.6: TP19.1@36.165,145.57 36.439,145.296 36.439,144.132 37.01,143.561 v4(37.01,143.507) R29.1@37.01,142.091 ; U3.7@52.25,141.011 52.25,140.586 53.146,139.691 54.047,139.691 55.118,138.62 C23.1@55.118,138.595 R33.2@56.769,138.595 56.755,138.609 56.755,139.677 v4(56.742,139.691)
  Layer 2 w0.6: v4(37.01,143.507) 40.826,139.691 v4(56.742,139.691)
NetC25_1: C25.1 D15.2 Q6.1 R38.2 | length 9.7
  Top Layer w0.4: R38.2@42.018,133.858 42.018,132.711 D15.2@42.645,132.084 43.786,130.943 C25.1@46.924,130.943 46.924,130.918 47.914,129.927 48.521,129.927 49.036,130.443 Q6.1@49.036,130.643
NetC26_1: C26.1 R34.1 | length 1.6
  Top Layer w0.4: R34.1@52.819,135.484 52.826,135.49 52.826,137.027 C26.1@52.832,137.033
NetC27_1: C27.1 Q5.1 R35.2 R47.1 U5.3 | length 10.2
  Top Layer w0.5: R47.1@82.243,57.104 82.209,57.139 80.62,57.139 C27.1@80.585,57.173 80.554,57.142 80.554,55.477 R35.2@80.523,55.446 80.548,55.446 81.505,54.49 81.505,53.7 82.017,53.188 U5.3@82.145,53.188 83.413,53.188 83.837,53.611 Q5.1@83.837,55.447
  Top Layer w0.7: Q5.1@83.837,55.447 Q5.1@83.838,55.448
NetC27_2: C27.2 D14.2 Q4.2 Q5.2 R32.2 R35.1 TP21.1 U5.4 | length 24.1
  Top Layer w0.5: D14.2@81.957,59.152 82.307,59.502 Q4.2@83.588,59.502 86.651,59.502 87.425,58.727 ; Q5.2@85.738,55.448 85.738,55.498 87.425,57.185 87.425,58.727 ; R32.2@89.13,57.023 89.13,57.048 88.905,57.273 88.88,57.273 87.425,58.727 ; R32.2@89.214,57.108 TP21.1@89.214,60.068
  Top Layer w0.7: U5.4@79.732,53.188 U5.4@79.605,53.188 79.586,53.188 79.173,53.6 79.173,54.327 79.073,54.427 79.073,55.321 78.948,55.446 R35.1@78.923,55.446 78.954,55.477 78.954,57.142 C27.2@78.985,57.173 79.01,57.173 79.535,57.698 79.535,57.876 80.812,59.152 D14.2@81.957,59.152 ; Q5.2@85.738,55.398 Q5.2@85.738,55.448 ; R32.2@89.005,56.873 89.13,56.998 R32.2@89.13,57.023 R32.2@89.214,57.108 ; TP21.1@89.214,60.068 TP21.1@89.299,60.152
NetC29_1: C29.1 R36.1 R42.2 U3.4 | length 6.3
  Top Layer w0.5: R42.2@45.847,138.214 C29.1@47.498,138.214 R36.1@49.099,138.214 49.06,138.253 49.06,139.939 48.44,140.559 U3.4@48.44,141.011
NetC30_1: C30.1 R37.1 R41.2 U3.9 | length 4.8
  Top Layer w0.6: U3.9@53.52,146.461 53.52,146.446 55.319,146.446 R41.2@55.334,146.431 ; C30.1@55.334,144.907 R41.2@55.334,146.431 ; R37.1@55.334,147.828 R41.2@55.334,146.431
NetC31_1: C31.1 R43.2 R46.2 U3.8 | length 11.9
  Top Layer w0.6: U3.8@53.52,141.011 57.681,141.011 58.42,140.272 C31.1@58.42,138.595 R46.2@59.944,138.595 60.119,138.77 60.119,139.033 62.015,140.93 R43.2@62.015,141.205
NetC33_1: C33.1 C42.2 C43.2 T1.7 | length 5.1
  Top Layer w0.7: C42.2@37.75,79.236 39.968,79.236 40.089,79.357
  Top Layer w1: 40.089,79.357 42.699,79.357 C43.2@42.799,79.457
NetC34_2: C34.2 R52.2
NetC45_2: C45.2 U6.3 | length 2
  Top Layer w0.6: C45.2@52.959,21.474 53.1,21.615 U6.3@54.892,21.615
NetC46_1: C46.1 Q12.2 U6.7 | length 16.7
  Top Layer w0.6: U6.7@60.342,22.885 59.009,22.885 58.235,23.659 C46.1@58.235,25.884 62.159,25.884 63.246,24.797 63.246,20.197 61.994,18.945 Q12.2@61.994,18.745
NetC47_2: C47.2 R62.2
NetC51_2: C51.2 D19.1 U7.14 | length 7.8
  Top Layer w0.5: U7.14@58.531,111.17 58.531,108.351 D19.1@59.474,107.408 61.705,107.408 62.59,108.292 C51.2@62.715,108.292
NetC53_2: C53.2 R64.2 R67.2 U7.6 | length 7.9
  Top Layer w0.5: R64.2@50.175,120.815 51.015,120.815 51.98,119.85 R67.2@52.705,119.85 52.731,119.824 54.222,119.824 C53.2@54.248,119.797 54.248,119.773 54.721,119.3 U7.6@54.721,116.57
NetC54_1: C54.1 R65.1 R70.2 R74.2 TP25.1 | length 9.2
  Top Layer w0.5: R74.2@92.473,35.164 92.548,35.089 94.442,35.089 R65.1@94.505,35.026 ; R70.2@94.433,36.825 R70.2@94.493,36.885 R70.2@94.505,36.873 ; C54.1@96.228,36.83 96.2,36.858 94.521,36.858 R70.2@94.505,36.873 ; TP25.1@97.536,34.163 97.121,34.163 96.27,35.014 R65.1@94.517,35.014 R65.1@94.505,35.026 ; R65.1@94.505,35.026 R70.2@94.505,36.873
NetC54_2: C54.2 R72.2 | length 1.7
  Top Layer w0.5: C54.2@97.828,36.83 R72.2@97.828,38.548
NetC56_2: C56.2 R69.2 R75.2 U7.7 | length 16.7
  Top Layer w0.5: v3(46.087,120.785) 46.102,120.8 46.974,120.8 R75.2@46.989,120.815 R69.2@48.514,120.815 ; v3(49.996,114.613) 49.977,114.632 49.977,115.247 C56.2@49.922,115.302 49.933,115.313 53.064,115.313 53.451,115.7 U7.7@53.451,116.57
  Layer 1 w0.5: v3(46.087,120.785) 46.087,116.472 47.946,114.613 v3(49.996,114.613)
NetC57_1: C57.1 R71.1 R76.2 U7.3 | length 14.9
  Top Layer w0.5: U7.3@58.531,116.57 58.538,116.578 58.538,118.335 R76.2@58.62,118.417 C57.1@60.2,118.417 59.975,118.192 59.975,117.841 59.817,117.683 v4(59.817,117.602) ; v4(61.695,126.352) R71.1@62.595,126.352
  Layer 1 w0.7: v4(59.817,117.602) 59.817,124.474 v4(61.695,126.352)
NetC58_1: C58.1 D20.2 R77.2 R79.2 U7.4 | length 9.9
  Top Layer w0.5: U7.4@57.261,116.57 57.261,120.999 R77.2@57.674,121.412 57.774,121.512 57.774,122.709 C58.1@57.874,122.809 R79.2@57.874,124.333 57.849,124.333 57.624,124.558 57.624,124.583 57.508,124.699 D20.2@57.508,126.002
NetC60_1: C60.1 D20.1 D21.1 R80.1 | length 6.5
  Top Layer w0.5: D20.1@59.708,126.002 60.989,124.721 60.989,124.469 R80.1@61.214,124.244 C60.1@62.738,124.244 64.369,124.244 D21.1@65.073,123.54
NetC61_1: C61.1 R81.1 | length 1.8
  Top Layer w0.5: C61.1@85.188,38.485 85.203,38.471 85.203,36.755 R81.1@85.217,36.741
NetC61_2: C61.2 C62.1 R78.1 U8.2 U9.1 | length 20
  Top Layer w0.5: U9.1@88.353,36.914 86.953,36.914 C62.1@86.803,36.764 86.796,36.771 86.796,38.478 C61.2@86.788,38.485 87.926,38.485 91.394,41.953 91.394,44.237 92.177,45.02 95.32,45.02 95.847,44.493 95.847,43.678 U8.2@95.862,43.663 95.885,43.639 95.885,42.097 95.516,41.728 95.516,41.703 95.291,41.478 R78.1@95.266,41.478
NetC62_2: C62.2 R74.1 R81.2 R83.1 R85.2 U9.2 | length 11.6
  Top Layer w0.5: R81.2@85.217,35.141 85.228,35.153 C62.2@86.791,35.153 ; R83.1@86.694,33.719 86.748,33.773 86.748,35.109 C62.2@86.791,35.153 ; U9.2@88.303,35.064 U9.2@88.353,35.014 ; R85.2@88.333,33.721 R85.2@88.336,33.724 88.344,33.732 U9.2@88.344,35.005 ; R74.1@92.473,36.764 89.898,36.764 89.605,36.471 89.605,35.332 89.299,35.026 88.365,35.026 U9.2@88.353,35.014 ; C62.2@86.791,35.153 C62.2@86.803,35.164 86.993,34.974 88.313,34.974 U9.2@88.344,35.005 ; U9.2@88.344,35.005 U9.2@88.353,35.014
NetC63_1: C63.1 Q14.1 R84.2 R86.1 | length 5.6
  Top Layer w0.5: Q14.1@88.628,28.646 88.678,28.696 C63.1@90.43,28.696 ; R84.2@90.64,27.051 90.64,28.616 90.56,28.696 C63.1@90.43,28.696 ; R86.1@92.291,28.848 92.282,28.857 90.609,28.857 C63.1@90.6,28.866 C63.1@90.43,28.696
NetC69_1: C69.1 R88.1 U10.30 | length 13.6
  Top Layer w0.25: 167.688,28.913 167.786,29.012 168.72,29.012 169.691,29.983 U10.30@169.691,30.595
  Top Layer w0.35: C69.1@164.63,26.416 164.93,26.716 165.49,26.716 167.688,28.913 167.688,28.915
  Top Layer w0.4: C69.1@164.63,26.416 164.652,26.394 164.652,25.713 v5(164.674,25.691) ; v5(166.37,21.59) 166.405,21.59 166.89,22.075 R88.1@166.89,22.225
  Layer 1 w0.4: v5(164.674,25.691) 166.37,23.995 v5(166.37,21.59)
NetC70_2: C70.2 R89.1 U10.29 | length 16
  Top Layer w0.25: 166.37,28.829 167.074,29.533 168.073,29.533 168.115,29.491 168.522,29.491 169.191,30.16 U10.29@169.191,30.595
  Top Layer w0.35: C70.2@164.674,27.944 164.749,28.019 164.749,28.624 164.954,28.829 166.37,28.829
  Top Layer w0.4: C70.2@164.674,27.944 v5(165.424,27.944) ; R89.1@164.833,22.225 164.833,22.075 165.318,21.59 v5(165.354,21.59)
  Layer 1 w0.4: v5(165.354,21.59) 165.354,21.671 165.741,22.059 165.741,23.734 164.563,24.912 164.351,24.912 163.83,25.433 163.83,26.35 v5(165.424,27.944)
NetC75_1: C75.1 C76.1 C77.1 C78.1 C79.1 Q17.5 Q17.6 Q17.7 Q17.8 Q17.9@146.028,52.757 Q19.5 Q19.6 Q19.7 Q19.8 Q19.9 R93.1 R96.2 | length 2.9
  Top Layer w0.4: R93.1@136.904,48.705 136.904,48.555 137.33,48.129 137.33,46.048 R96.2@137.404,45.974
  other v1: 135.89,45.085 139.065,45.085 139.065,46.355
  other v2: 124.46,40.005 124.46,41.275 124.46,42.545 121.92,43.815
  other v3: 156.845,41.529 157.734,41.529 156.845,42.291 157.734,42.291 156.845,43.053 157.734,43.053
NetC80_1: C80.1 L8.1 Q20.1 Q20.2 Q20.3 Q21.5 Q21.6 Q21.7 Q21.8 Q21.9 U10.28 | length 19.2
  Top Layer w0.25: v5(166.661,30.611) 167.732,30.611 168.366,31.245 U10.28@168.541,31.245
  Top Layer w0.4: v4(160.019,28.879) C80.1@160.019,29.901
  Bottom Layer w0.25: 164.083,30.701 164.808,30.701 165.013,30.495 165.884,30.495 165.936,30.547 166.597,30.547 v5(166.661,30.611)
  Bottom Layer w0.4: 153.318,24.478 153.45,24.478 156.401,27.429 156.972,27.429 158.422,28.879 v4(160.019,28.879) 160.095,28.956 160.752,28.956 162.497,30.701 164.083,30.701
  other v2: 147.32,25.4 149.86,25.4 148.59,26.67 149.86,27.94
  other v3: 151.268,24.478 152.018,24.478 152.793,24.478 151.268,25.273 152.018,25.273 152.793,25.273
NetC80_2: C80.2 D23.1 U10.26 | length 14.1
  Top Layer w0.25: v5(165.862,31.877) 166.788,31.877 167.111,32.2 167.716,32.2 167.761,32.245 U10.26@168.541,32.245
  Top Layer w0.4: D23.1@156.293,32.485 157.277,31.501 C80.2@160.019,31.501
  Top Layer w0.6: C80.2@160.019,31.501 v5(160.019,32.251)
  Bottom Layer w0.4: v5(160.019,32.251) 160.028,32.251 160.537,32.76 164.979,32.76 v5(165.862,31.877)
NetC81_1: C81.1 L8.2 Q19.1 Q19.2 Q19.3 Q22.5 Q22.6 Q22.7 Q22.8 Q22.9 U10.18 | length 18.9
  Top Layer w0.25: C81.1@164.05,36.722 164.14,36.812 164.828,36.812 169.044,36.812 169.191,36.666 U10.18@169.191,36.395
  Top Layer w0.4: C81.1@164.14,36.812 C81.1@164.176,36.776 ; v5@164.792,36.776 164.828,36.812 v5(164.846,36.83)
  Top Layer w0.5: C81.1@164.176,36.776 v5@164.792,36.776
  Bottom Layer w0.4: 153.297,39.367 155.834,36.83 v5(164.846,36.83)
  other v2: 150.495,36.195 151.765,37.465 150.495,38.735 153.035,38.735
  other v3: 151.511,41.148 153.162,41.148 152.343,41.179 151.511,42.037 152.343,42.037 153.162,42.037
NetC81_2: C81.2 D24.1 U10.20 | length 14.1
  Top Layer w0.25: v5(164.846,35.179) 165.664,35.997 166.843,35.997 167.595,35.245 U10.20@168.541,35.245
  Top Layer w0.4: D24.1@156.293,34.384 156.313,34.363 157.091,34.363 157.526,34.798 v5(157.607,34.798) ; C81.2@164.05,35.122 C81.2@164.078,35.15 ; v5@164.817,35.15 v5(164.846,35.179)
  Top Layer w0.5: C81.2@164.078,35.15 v5@164.817,35.15
  Bottom Layer w0.4: v5(157.607,34.798) 157.688,34.798 158.069,35.179 v5(164.846,35.179)
NetC82_2: C82.2 R93.2 U10.14 | length 53.6
  Top Layer w0.25: U10.14@171.191,36.395 171.191,37.412 171.482,37.703 v5(171.482,37.824)
  Top Layer w0.4: v4(134.954,47.924) 135.031,48.001 135.031,48.181 135.404,48.555 R93.2@135.404,48.705 ; C82.2@165.061,39.972 165.089,39.944 165.089,38.802 v5(165.117,38.774)
  Layer 1 w0.4: v4(134.954,47.924) 143.67,47.924 143.67,47.823 145.275,46.218 165.14,46.218 172.067,39.292 172.067,38.491 171.482,37.906 v5(171.482,37.824) v5@171.539,37.882
  Layer 2 w0.4: v5(165.117,38.774) 165.79,38.1 167.883,38.1 168.687,37.296 170.872,37.296 171.4,37.824 v5(171.482,37.824) v5@171.539,37.882
NetC83_1: C83.1 R97.2 U10.13 | length 47.1
  Top Layer w0.25: C83.1@170.217,39.972 170.242,39.972 171.244,38.969 v5(171.288,38.969) 171.332,38.969 172.185,38.116 172.185,37.533 171.691,37.038 U10.13@171.691,36.395
  Top Layer w0.4: R97.2@133.354,48.705 133.354,48.555 133.703,48.206 133.703,48.001 v4(133.78,47.924)
  Layer 1 w0.4: v4(133.78,47.924) 134.608,47.095 135.297,47.095 135.497,47.295 143.309,47.295 145.014,45.59 164.88,45.59 170.099,40.37 170.844,39.625 170.844,39.494 171.288,39.05 v5(171.288,38.969)
NetC91_1: C91.1 U11.1 | length 1.8
  Top Layer w0.4: U11.1@178.454,55.06 179.135,55.06 179.304,54.892 180.019,54.892 C91.1@180.144,54.767
NetC91_2: C91.2 L9.1 U11.6
NetC92_2: C92.2 J8.2 J8.4 J8.6 U11.4 U11.5 | length 47.5
  Top Layer w0.8: J8.2@134.79,64.008 J8.4@137.33,64.008 J8.6@139.87,64.008
  Layer 1 w0.4: v4(152.633,62.357) 153.949,61.041 153.949,56.897 155.189,55.657 158.693,55.657 160.019,54.332 160.019,52.327 160.639,51.707 172.049,51.707 172.067,51.689 172.215,51.837 172.923,51.837 v2(173.019,51.933)
  Layer 2 w0.4: J8.6@139.87,64.008 139.994,64.132 151.524,64.132 152.633,63.023 v4(152.633,62.357)
NetC94_1: C94.1 C96.2 D34.1 U12.6 | length 10.3
  Top Layer w0.6: D34.1@87.044,111.639 87.187,111.497 87.928,111.497 88.279,111.145 U12.6@88.279,109.512 88.279,108.177 88.491,107.965 90.144,107.965 90.179,107.931 C96.2@91.743,107.931 91.785,107.889 93.845,107.889 C94.1@93.886,107.848 C94.1@93.815,107.777
NetC94_2: C94.2 C95.1 C96.1 D36.1 L10.1 R118.1 R119.1 U12.1 U12.2 U12.3 | length 13.8
  Top Layer w0.2: 93.233,103.493 93.233,104.398 93.783,104.948 C94.2@93.886,104.948
  Top Layer w0.6: U12.3@88.279,104.062 88.279,104.997 89.613,106.331 C96.1@91.743,106.331 ; R118.1@92.157,109.755 R118.1@92.157,109.854 93.965,109.854 C95.1@94.082,109.737
  Top Layer w0.8: D36.1@84.805,101.161 86.754,101.161 86.835,101.242 ; L10.1@92.07,99.835 92.838,100.602 v1(92.838,102.4)
  other v1: 87.077,102.625 88.101,102.625 93.233,109.837
NetC95_2: C95.2 D34.2 D35.1 R116.1 R132.1 | length 14.6
  Top Layer w0.6: D34.2@89.244,111.639 89.244,112.028 89.94,112.723 92.184,112.723 92.543,112.364 R132.1@92.543,111.639 93.679,111.639 C95.2@94.082,111.237 94.415,111.57 R116.1@96.749,111.57 96.822,111.497 99.29,111.497 99.968,110.818 D35.1@99.968,109.131
NetC101_1: C101.1 J9.26 R125.1 R126.2 | length 6.2
  Top Layer w0.4: C101.1@195.999,60.452 R125.1@195.999,62.103 ; R126.2@195.999,63.754 R125.1@195.999,62.103 ; J9.26@198.882,61.976 198.819,62.039 196.063,62.039 R125.1@195.999,62.103
NetC102_1: C102.1 J9.25 R127.1 R130.1 | length 6.6
  Top Layer w0.4: R130.1@195.999,55.171 R127.1@195.999,56.896 C102.1@195.999,58.547 196.024,58.547 196.913,59.436 J9.25@198.882,59.436
NetC103_1: C103.1 J9.24 R128.1 R129.1 | length 8.1
  Top Layer w0.4: R129.1@195.999,50.033 R128.1@195.999,51.689 C103.1@195.999,53.397 196.024,53.397 198.658,56.031 198.658,56.672 J9.24@198.882,56.896
NetD2_1: D2.1 R1.2 | length 2.4
  Top Layer w0.6: R1.2@62.656,150.468 D2.1@64.985,150.468 ; 64.604,150.468 64.686,150.55
NetD2_2: D2.2 Q1.1 R2.2 R3.2 TP6.1 | length 8.7
  Top Layer w0.4: TP6.1@62.595,145.168 62.701,145.273 64.211,145.273 67.033,148.095 R3.2@67.033,148.26 ; Q1.1@65.382,153.814 65.525,153.67 R2.2@67.122,153.67
  Top Layer w0.8: Q1.1@65.382,152.728 Q1.1@65.382,153.814
NetD3_2: D3.2 D6.2 L4.3
NetD3_3: D3.3 D5.2 L4.2
NetD5_1: D5.1 D6.1 R8.2 | length 5.8
  Top Layer w0.6: R8.2@26.162,89.842 26.165,89.845 D6.1@26.165,92.329 D5.1@26.165,95.606
NetD7_1: D7.1 R7.1 | length 3.3
  Top Layer w0.5: R7.1@94.336,66.477 95.086,66.477 95.114,66.505 95.206,66.505 95.498,66.798 D7.1@95.498,68.79
NetD7_2: D7.2 R13.2 U1.3 | length 6.5
  Top Layer w0.5: U1.3@91.346,70.329 93.73,70.329 94.392,70.99 D7.2@95.498,70.99 96.867,70.99 97.322,71.446 R13.2@97.347,71.446
NetD8_3: D8.3 L5.5 Q3.2 TP12.1 | length 14.2
  Top Layer w1: Q3.2@33.43,164.12 36.84,160.71 43.29,160.71 45.026,158.974 D8.3@45.026,158.474
NetD10_1: D10.1 R7.2 TP11.1 U1.1 | length 8.3
  Top Layer w0.5: D10.1@91.119,63.744 92.443,63.744 92.628,63.928 ; U1.1@91.346,67.789 92.29,67.789 92.736,67.342 R7.2@92.736,66.477 92.736,64.037 92.628,63.928 ; TP11.1@94.312,63.928 92.628,63.928
NetD11_1: D11.1 R15.2 | length 2.4
  Top Layer w0.5: D11.1@33.644,150.69 33.839,150.495 R15.2@35.928,150.495
NetD11_2: D11.2 Q3.1 R17.2 R18.2 TP13.1
NetD12_1: D12.1 R22.1 U1.5 | length 4.6
  Top Layer w0.5: D12.1@83.16,71.89 83.451,71.599 U1.5@85.946,71.599 85.924,71.621 85.924,73.239 R22.1@85.901,73.262
NetD12_2: D12.2 R23.1 | length 1.8
  Top Layer w0.5: R23.1@81.419,69.541 81.517,69.64 83.11,69.64 D12.2@83.16,69.69
NetD13_1: D13.1 R23.2 TP16.1 U1.7 | length 10.5
  Top Layer w0.5: TP16.1@78.88,65.728 79.064,65.913 79.064,67.494 79.487,67.916 R23.2@81.419,67.916 ; R23.2@81.419,67.941 R23.2@81.419,67.916 ; U1.7@85.946,69.059 84.643,69.059 84.35,68.766 84.35,67.688 84.057,67.395 D13.1@83.16,67.395 81.94,67.395 R23.2@81.419,67.916
NetD16_2: D16.2 R50.1 | length 4
  Top Layer w0.5: R50.1@55.118,99.187 55.484,98.821 56.317,98.821 57.459,97.679 D16.2@57.459,96.679
NetD17_2: D17.2 R54.1 | length 7.7
  Top Layer w0.7: R54.1@40.386,101.459 45.154,101.459 46.029,100.584 D17.2@47.715,100.584
NetD18_1: D18.1 Q12.1 R60.1 | length 3.9
  Top Layer w0.6: Q12.1@63.894,18.745 64.919,18.745 65.535,18.129 R60.1@65.535,18.104 65.594,18.045 D18.1@67.48,18.045
NetD19_2: D19.2 R63.1 | length 3
  Top Layer w0.8: R63.1@56.515,103.408 D19.2@59.474,103.408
